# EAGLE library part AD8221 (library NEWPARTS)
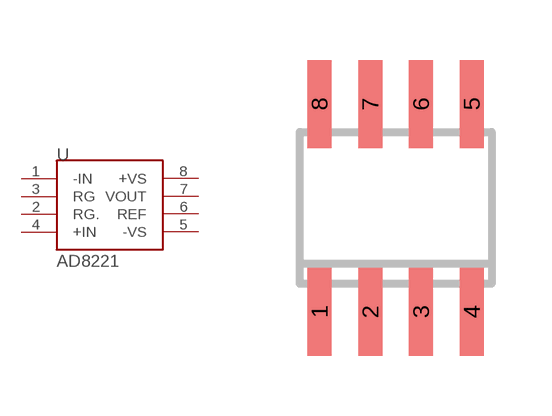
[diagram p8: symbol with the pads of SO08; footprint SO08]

Designator prefix -

## AD8221  [SO08]
1  -IN
2  RG.
3  RG
4  +IN
5  -VS
6  REF
7  VOUT
8  +VS

## Footprint SO08 (pad centres in mm)
Small Outline Package 8 NS Package M08A
smd 0.6 x 2.2: 1 -1.905,-2.6; 2 -0.635,-2.6; 3 0.635,-2.6; 4 1.905,-2.6; 5 1.905,2.6; 6 0.635,2.6; 7 -0.635,2.6; 8 -1.905,2.6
